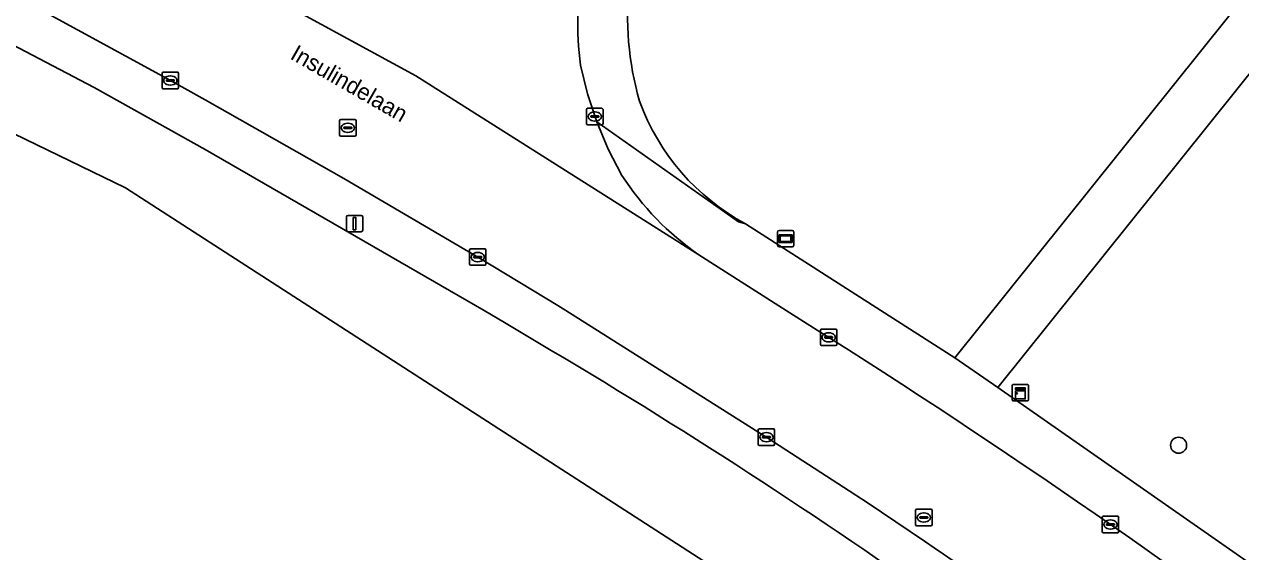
# Model space of a CAD drawing. Extents: x 162417 to 163722, y 384268 to 385417.
# Drawn here: x 162489 to 162563, y 384735.3 to 384767.4 of the extents above; entities that cross this region are included whole.
import ezdxf

# ---------------------------------------------------------------- set-up
doc = ezdxf.new("R2010")
doc.units = 0
for name, color, linetype in [('IMGEO_Berm_groen', 7, 'Continuous'), ('IMGEO_Boom', 7, 'Continuous'), ('IMGEO_Groenvoorziening', 7, 'Continuous'), ('IMGEO_Kast', 7, 'Continuous'), ('IMGEO_Kolk', 7, 'Continuous'), ('IMGEO_Lichtmast', 7, 'Continuous'), ('IMGEO_Openbare_ruimte_label', 7, 'Continuous'), ('IMGEO_Rijbaan_lokaal_open', 7, 'Continuous'), ('IMGEO_Rijbaan_regionaal_gesloten', 7, 'Continuous'), ('IMGEO_Rioolput', 7, 'Continuous'), ('IMGEO_Voetpad_gesloten', 7, 'Continuous'), ('IMGEO_Voetpad_open', 7, 'Continuous'), ('IMGEO_Wegwijzer', 7, 'Continuous')]:
    doc.layers.add(name, color=color, linetype=linetype)

msp = doc.modelspace()

# ---------------------------------------------------------------- linework, layer by layer
at = {"layer": 'IMGEO_Berm_groen'}
for points in [[(162466.355, 384777.285), (162477.959, 384771.545), (162479.839, 384770.588), (162493.238, 384763.558), (162500, 384759.787), (162516.963, 384750), (162518.198, 384749.269), (162519.432, 384748.535)], [(162543.752, 384735.979), (162540.261, 384738.331), (162534.228, 384742.243), (162521.936, 384750), (162521.444, 384750.302), (162516.728, 384753.165), (162508.438, 384758.029), (162500, 384762.81), (162497.883, 384763.979), (162489.507, 384768.547), (162481.057, 384772.976), (162479.187, 384773.932)]]:
    msp.add_lwpolyline(points, dxfattribs=at)
for centre, radius, start, end in [((162335.409, 384435.223), 363.358, 54.81641, 59.57224), ((162200.568, 384229.882), 611.482, 53.733687, 55.858809)]:
    msp.add_arc(centre, radius, start, end, dxfattribs=at)
at = {"layer": 'IMGEO_Boom'}
msp.add_circle((162559.218, 384741.808), 0.489, dxfattribs=at)
at = {"layer": 'IMGEO_Groenvoorziening'}
for points in [[(162532.879, 384755.269), (162541.11, 384750), (162545.602, 384747.124), (162593.733, 384807.099)], [(162619.678, 384785.416), (162615.926, 384792.421), (162606.136, 384786.338), (162595.297, 384803.992), (162568.435, 384770.521), (162570.041, 384769.255), (162570.101, 384769.331), (162571.485, 384768.241), (162570.384, 384766.843), (162569, 384767.934), (162569.063, 384768.014), (162567.447, 384769.289), (162548.211, 384745.32), (162564.266, 384734.123)]]:
    msp.add_lwpolyline(points, dxfattribs=at)
for centre, radius, start, end in [((162544.214, 384767.888), 18.521, 173.44315, 196.21945), ((162539.387, 384767.421), 13.785, 199.96267, 241.82917)]:
    msp.add_arc(centre, radius, start, end, dxfattribs=at)
at = {"layer": 'IMGEO_Kast'}
for p, q in [((162549.091, 384744.577), (162549.091, 384745.418)), ((162549.091, 384745.418), (162549.091, 384744.577)), ((162549.166, 384745.502), (162550.007, 384745.502)), ((162550.007, 384745.502), (162549.166, 384745.502)), ((162550.091, 384745.427), (162550.091, 384744.586)), ((162550.091, 384744.586), (162550.091, 384745.427)), ((162550.016, 384744.502), (162549.175, 384744.502)), ((162549.175, 384744.502), (162550.016, 384744.502))]:
    msp.add_line(p, q, dxfattribs=at)
for points in [[(162549.286, 384745.292), (162549.886, 384745.292), (162549.886, 384745.207), (162549.286, 384745.207), (162549.286, 384745.292)], [(162549.286, 384745.117), (162549.886, 384745.117), (162549.886, 384744.628), (162549.286, 384744.628), (162549.286, 384745.117)]]:
    msp.add_lwpolyline(points, dxfattribs=at)
msp.add_circle((162549.37, 384744.966), 0.0377, dxfattribs=at)
for centre, start, end in [((162549.169, 384745.424), 92.4484, 184.28452), ((162549.169, 384745.424), 92.4484, 184.28452), ((162550.013, 384745.424), 2.4484, 94.28452), ((162550.013, 384745.424), 2.4484, 94.28452), ((162549.169, 384744.58), 182.4484, 274.28452), ((162549.169, 384744.58), 182.4484, 274.28452), ((162550.013, 384744.58), 272.4484, 4.28452), ((162550.013, 384744.58), 272.4484, 4.28452)]:
    msp.add_arc(centre, 0.0779, start, end, dxfattribs=at)
at = {"layer": 'IMGEO_Kolk'}
for p, q in [((162497.453, 384764.48), (162498.305, 384764.48)), ((162497.378, 384763.554), (162497.378, 384764.406)), ((162497.637, 384763.974), (162497.637, 384763.986)), ((162498.075, 384763.937), (162497.677, 384763.937)), ((162497.68, 384764.023), (162498.078, 384764.023)), ((162497.866, 384764.26), (162497.891, 384764.26)), ((162498.121, 384763.986), (162498.121, 384763.974)), ((162498.379, 384764.406), (162498.379, 384763.554)), ((162498.305, 384763.48), (162497.453, 384763.48)), ((162497.889, 384763.7), (162497.864, 384763.7)), ((162523.276, 384762.29), (162524.128, 384762.29)), ((162523.201, 384761.364), (162523.201, 384762.216)), ((162523.46, 384761.784), (162523.46, 384761.796)), ((162523.898, 384761.747), (162523.5, 384761.747)), ((162523.503, 384761.833), (162523.901, 384761.833)), ((162523.712, 384761.51), (162523.687, 384761.51)), ((162523.689, 384762.07), (162523.714, 384762.07)), ((162523.944, 384761.796), (162523.944, 384761.784)), ((162524.202, 384762.216), (162524.202, 384761.364)), ((162524.128, 384761.29), (162523.276, 384761.29)), ((162516.079, 384752.82), (162516.079, 384753.672)), ((162516.154, 384753.746), (162517.006, 384753.746)), ((162516.567, 384753.526), (162516.592, 384753.526)), ((162517.08, 384753.672), (162517.08, 384752.82)), ((162517.006, 384752.746), (162516.154, 384752.746)), ((162516.338, 384753.24), (162516.338, 384753.252)), ((162516.776, 384753.203), (162516.378, 384753.203)), ((162516.381, 384753.289), (162516.779, 384753.289)), ((162516.59, 384752.966), (162516.565, 384752.966)), ((162516.822, 384753.252), (162516.822, 384753.24)), ((162537.428, 384747.94), (162537.428, 384748.792)), ((162537.503, 384748.866), (162538.355, 384748.866)), ((162537.687, 384748.36), (162537.687, 384748.372)), ((162538.125, 384748.323), (162537.727, 384748.323)), ((162537.73, 384748.409), (162538.128, 384748.409)), ((162537.916, 384748.646), (162537.941, 384748.646)), ((162538.171, 384748.372), (162538.171, 384748.36)), ((162538.429, 384748.792), (162538.429, 384747.94)), ((162538.355, 384747.866), (162537.503, 384747.866)), ((162537.939, 384748.086), (162537.914, 384748.086)), ((162533.642, 384741.873), (162533.642, 384742.725)), ((162533.717, 384742.799), (162534.569, 384742.799)), ((162533.901, 384742.293), (162533.901, 384742.305)), ((162534.339, 384742.256), (162533.941, 384742.256)), ((162533.944, 384742.342), (162534.342, 384742.342)), ((162534.13, 384742.579), (162534.155, 384742.579)), ((162534.385, 384742.305), (162534.385, 384742.293)), ((162534.643, 384742.725), (162534.643, 384741.873)), ((162534.569, 384741.799), (162533.717, 384741.799)), ((162534.153, 384742.019), (162534.128, 384742.019)), ((162554.57, 384736.564), (162554.57, 384737.416)), ((162554.645, 384737.49), (162555.497, 384737.49)), ((162555.058, 384737.27), (162555.083, 384737.27)), ((162555.571, 384737.416), (162555.571, 384736.564)), ((162555.497, 384736.49), (162554.645, 384736.49)), ((162554.829, 384736.984), (162554.829, 384736.996)), ((162555.267, 384736.947), (162554.869, 384736.947)), ((162554.872, 384737.033), (162555.27, 384737.033)), ((162555.081, 384736.71), (162555.056, 384736.71)), ((162555.313, 384736.996), (162555.313, 384736.984))]:
    msp.add_line(p, q, dxfattribs=at)
for points in [[(162497.453, 384764.48), (162498.305, 384764.48)], [(162497.378, 384763.554), (162497.378, 384764.406)], [(162498.379, 384764.406), (162498.379, 384763.554)], [(162498.305, 384763.48), (162497.453, 384763.48)], [(162523.276, 384762.29), (162524.128, 384762.29)], [(162523.201, 384761.364), (162523.201, 384762.216)], [(162524.202, 384762.216), (162524.202, 384761.364)], [(162524.128, 384761.29), (162523.276, 384761.29)], [(162516.079, 384752.82), (162516.079, 384753.672)], [(162516.154, 384753.746), (162517.006, 384753.746)], [(162517.08, 384753.672), (162517.08, 384752.82)], [(162517.006, 384752.746), (162516.154, 384752.746)], [(162537.428, 384747.94), (162537.428, 384748.792)], [(162537.503, 384748.866), (162538.355, 384748.866)], [(162538.429, 384748.792), (162538.429, 384747.94)], [(162538.355, 384747.866), (162537.503, 384747.866)], [(162533.642, 384741.873), (162533.642, 384742.725)], [(162533.717, 384742.799), (162534.569, 384742.799)], [(162534.643, 384742.725), (162534.643, 384741.873)], [(162534.569, 384741.799), (162533.717, 384741.799)], [(162554.57, 384736.564), (162554.57, 384737.416)], [(162554.645, 384737.49), (162555.497, 384737.49)], [(162555.571, 384737.416), (162555.571, 384736.564)], [(162555.497, 384736.49), (162554.645, 384736.49)]]:
    msp.add_lwpolyline(points, dxfattribs=at)
for centre, radius, start, end in [((162497.455, 384764.404), 0.0765, 91.55205, 178.44795), ((162497.455, 384764.404), 0.0765, 91.55205, 178.44795), ((162498.303, 384764.404), 0.0765, 1.55205, 88.44795), ((162498.303, 384764.404), 0.0765, 1.55205, 88.44795), ((162497.677, 384763.983), 0.0403, 85.87752, 175.75265), ((162497.674, 384763.973), 0.0366, 178.93798, 274.71019), ((162498.078, 384763.98), 0.043, 264.86636, 352.45326), ((162498.082, 384763.985), 0.0386, 1.73085, 96.63898), ((162497.455, 384763.556), 0.0765, 181.55205, 268.44795), ((162497.455, 384763.556), 0.0765, 181.55205, 268.44795), ((162498.303, 384763.556), 0.0765, 271.55205, 358.44795), ((162498.303, 384763.556), 0.0765, 271.55205, 358.44795), ((162523.278, 384762.214), 0.0765, 91.55205, 178.44795), ((162523.278, 384762.214), 0.0765, 91.55205, 178.44795), ((162524.126, 384762.214), 0.0765, 1.55205, 88.44795), ((162524.126, 384762.214), 0.0765, 1.55205, 88.44795), ((162523.5, 384761.793), 0.0403, 85.87752, 175.75265), ((162523.497, 384761.783), 0.0366, 178.93798, 274.71019), ((162523.901, 384761.79), 0.043, 264.86636, 352.45326), ((162523.905, 384761.795), 0.0386, 1.73085, 96.63898), ((162523.278, 384761.366), 0.0765, 181.55205, 268.44795), ((162523.278, 384761.366), 0.0765, 181.55205, 268.44795), ((162524.126, 384761.366), 0.0765, 271.55205, 358.44795), ((162524.126, 384761.366), 0.0765, 271.55205, 358.44795), ((162516.156, 384753.67), 0.0765, 91.55205, 178.44795), ((162516.156, 384753.67), 0.0765, 91.55205, 178.44795), ((162517.004, 384753.67), 0.0765, 1.55205, 88.44795), ((162517.004, 384753.67), 0.0765, 1.55205, 88.44795), ((162516.156, 384752.822), 0.0765, 181.55205, 268.44795), ((162516.156, 384752.822), 0.0765, 181.55205, 268.44795), ((162516.378, 384753.249), 0.0403, 85.87752, 175.75265), ((162516.375, 384753.239), 0.0366, 178.93798, 274.71019), ((162516.779, 384753.246), 0.043, 264.86636, 352.45326), ((162516.783, 384753.251), 0.0386, 1.73085, 96.63898), ((162517.004, 384752.822), 0.0765, 271.55205, 358.44795), ((162517.004, 384752.822), 0.0765, 271.55205, 358.44795), ((162537.505, 384748.79), 0.0765, 91.55205, 178.44795), ((162537.505, 384748.79), 0.0765, 91.55205, 178.44795), ((162537.727, 384748.369), 0.0403, 85.87752, 175.75265), ((162537.724, 384748.359), 0.0366, 178.93798, 274.71019), ((162538.128, 384748.366), 0.043, 264.86636, 352.45326), ((162538.132, 384748.371), 0.0386, 1.73085, 96.63898), ((162538.353, 384748.79), 0.0765, 1.55205, 88.44795), ((162538.353, 384748.79), 0.0765, 1.55205, 88.44795), ((162537.505, 384747.942), 0.0765, 181.55205, 268.44795), ((162537.505, 384747.942), 0.0765, 181.55205, 268.44795), ((162538.353, 384747.942), 0.0765, 271.55205, 358.44795), ((162538.353, 384747.942), 0.0765, 271.55205, 358.44795), ((162533.719, 384742.723), 0.0765, 91.55205, 178.44795), ((162533.719, 384742.723), 0.0765, 91.55205, 178.44795), ((162533.941, 384742.302), 0.0403, 85.87752, 175.75265), ((162533.938, 384742.292), 0.0366, 178.93798, 274.71019), ((162534.342, 384742.299), 0.043, 264.86636, 352.45326), ((162534.346, 384742.304), 0.0386, 1.73085, 96.63898), ((162534.567, 384742.723), 0.0765, 1.55205, 88.44795), ((162534.567, 384742.723), 0.0765, 1.55205, 88.44795), ((162533.719, 384741.875), 0.0765, 181.55205, 268.44795), ((162533.719, 384741.875), 0.0765, 181.55205, 268.44795), ((162534.567, 384741.875), 0.0765, 271.55205, 358.44795), ((162534.567, 384741.875), 0.0765, 271.55205, 358.44795), ((162554.647, 384737.414), 0.0765, 91.55205, 178.44795), ((162554.647, 384737.414), 0.0765, 91.55205, 178.44795), ((162555.495, 384737.414), 0.0765, 1.55205, 88.44795), ((162555.495, 384737.414), 0.0765, 1.55205, 88.44795), ((162554.647, 384736.566), 0.0765, 181.55205, 268.44795), ((162554.647, 384736.566), 0.0765, 181.55205, 268.44795), ((162554.869, 384736.993), 0.0403, 85.87752, 175.75265), ((162554.866, 384736.983), 0.0366, 178.93798, 274.71019), ((162555.27, 384736.99), 0.043, 264.86636, 352.45326), ((162555.274, 384736.995), 0.0386, 1.73085, 96.63898), ((162555.495, 384736.566), 0.0765, 271.55205, 358.44795), ((162555.495, 384736.566), 0.0765, 271.55205, 358.44795)]:
    msp.add_arc(centre, radius, start, end, dxfattribs=at)
for centre, major_axis, ratio, start_param, end_param in [((162497.865, 384763.98), (-0.387, 0.002), 0.722429, 4.712389, 7.853982), ((162497.89, 384763.98), (-0.39, 0.002), 0.717154, 1.570796, 4.712389), ((162523.688, 384761.79), (-0.387, 0.002), 0.722429, 4.712389, 7.853982), ((162523.713, 384761.79), (-0.39, 0.002), 0.717154, 1.570796, 4.712389), ((162516.566, 384753.246), (-0.387, 0.002), 0.722429, 4.712389, 7.853982), ((162516.591, 384753.246), (-0.39, 0.002), 0.717154, 1.570796, 4.712389), ((162537.915, 384748.366), (-0.387, 0.002), 0.722429, 4.712389, 7.853982), ((162537.94, 384748.366), (-0.39, 0.002), 0.717154, 1.570796, 4.712389), ((162534.129, 384742.299), (-0.387, 0.002), 0.722429, 4.712389, 7.853982), ((162534.154, 384742.299), (-0.39, 0.002), 0.717154, 1.570796, 4.712389), ((162555.057, 384736.99), (-0.387, 0.002), 0.722429, 4.712389, 7.853982), ((162555.082, 384736.99), (-0.39, 0.002), 0.717154, 1.570796, 4.712389)]:
    msp.add_ellipse(centre, major_axis=major_axis, ratio=ratio, start_param=start_param, end_param=end_param, dxfattribs=at)
at = {"layer": 'IMGEO_Lichtmast'}
for p, q in [((162508.59, 384754.884), (162508.59, 384755.684)), ((162508.59, 384755.684), (162508.59, 384754.884)), ((162508.69, 384755.784), (162509.48, 384755.784)), ((162509.48, 384755.784), (162508.69, 384755.784)), ((162509.58, 384755.684), (162509.58, 384754.884)), ((162509.58, 384754.884), (162509.58, 384755.684)), ((162509.48, 384754.784), (162508.69, 384754.784)), ((162508.69, 384754.784), (162509.48, 384754.784))]:
    msp.add_line(p, q, dxfattribs=at)
msp.add_lwpolyline([(162509.01, 384755.659), (162509.16, 384755.659), (162509.16, 384754.909), (162509.01, 384754.909), (162509.01, 384755.659)], dxfattribs=at)
for centre, start, end in [((162508.69, 384755.684), 90, 180), ((162508.69, 384755.684), 90, 180), ((162509.48, 384755.684), 0, 90), ((162509.48, 384755.684), 360, 90), ((162508.69, 384754.884), 180, 270), ((162508.69, 384754.884), 180, 270), ((162509.48, 384754.884), 270, 0), ((162509.48, 384754.884), 270, 0)]:
    msp.add_arc(centre, 0.1, start, end, dxfattribs=at)
at = {"layer": 'IMGEO_Rijbaan_lokaal_open'}
for points in [[(162539.129, 384747.613), (162537.23, 384748.802), (162535.35, 384750), (162531.214, 384752.635), (162530.024, 384753.387), (162512.819, 384764.272), (162493.067, 384775.022), (162489.507, 384768.547), (162497.883, 384763.979), (162500, 384762.81), (162508.438, 384758.029), (162516.728, 384753.165), (162521.444, 384750.302), (162521.936, 384750), (162534.228, 384742.243), (162540.261, 384738.331), (162543.752, 384735.979)], [(162496.132, 384774.163), (162494.962, 384774.352), (162494.006, 384774.664), (162493.067, 384775.022), (162512.819, 384764.272), (162530.024, 384753.387)], [(162525.353, 384758.214), (162524.522, 384759.807), (162523.822, 384761.461), (162523.257, 384763.166), (162522.832, 384764.911)]]:
    msp.add_lwpolyline(points, dxfattribs=at)
for centre, radius, start, end in [((162544.798, 384767.627), 22.134, 170.98768, 187.04798), ((162539.787, 384767.508), 17.167, 212.77721, 235.34085), ((162270.319, 384326.926), 499.236, 52.69511, 57.4223), ((162200.568, 384229.882), 611.482, 53.733687, 55.858809)]:
    msp.add_arc(centre, radius, start, end, dxfattribs=at)
at = {"layer": 'IMGEO_Rijbaan_regionaal_gesloten'}
for points in [[(162438.86, 384789.831), (162436.975, 384790.606), (162434.087, 384786.412), (162434.087, 384786.412), (162440.149, 384784.123), (162495.159, 384757.46), (162560.661, 384715.197), (162604.045, 384676.904), (162623.61, 384658.183), (162629.086, 384651.951)], [(162519.432, 384748.535), (162518.198, 384749.269), (162516.963, 384750), (162500, 384759.787), (162493.238, 384763.558), (162479.839, 384770.588), (162477.959, 384771.545), (162466.355, 384777.285)]]:
    msp.add_lwpolyline(points, dxfattribs=at)
msp.add_arc((162335.409, 384435.223), 363.358, 54.81641, 59.57224, dxfattribs=at)
at = {"layer": 'IMGEO_Rioolput'}
for p, q in [((162508.176, 384760.678), (162508.176, 384761.53)), ((162508.251, 384761.604), (162509.103, 384761.604)), ((162509.177, 384761.53), (162509.177, 384760.678)), ((162508.435, 384761.098), (162508.435, 384761.11)), ((162508.873, 384761.061), (162508.475, 384761.061)), ((162508.478, 384761.147), (162508.876, 384761.147)), ((162508.687, 384760.824), (162508.662, 384760.824)), ((162508.664, 384761.384), (162508.689, 384761.384)), ((162508.919, 384761.11), (162508.919, 384761.098)), ((162509.103, 384760.604), (162508.251, 384760.604)), ((162543.216, 384736.991), (162543.216, 384737.843)), ((162543.291, 384737.917), (162544.143, 384737.917)), ((162544.217, 384737.843), (162544.217, 384736.991)), ((162543.475, 384737.411), (162543.475, 384737.423)), ((162543.913, 384737.374), (162543.515, 384737.374)), ((162543.518, 384737.46), (162543.916, 384737.46)), ((162543.727, 384737.137), (162543.702, 384737.137)), ((162543.704, 384737.697), (162543.729, 384737.697)), ((162543.959, 384737.423), (162543.959, 384737.411)), ((162544.143, 384736.917), (162543.291, 384736.917))]:
    msp.add_line(p, q, dxfattribs=at)
for points in [[(162508.176, 384760.678), (162508.176, 384761.53)], [(162508.251, 384761.604), (162509.103, 384761.604)], [(162509.177, 384761.53), (162509.177, 384760.678)], [(162509.103, 384760.604), (162508.251, 384760.604)], [(162543.216, 384736.991), (162543.216, 384737.843)], [(162543.291, 384737.917), (162544.143, 384737.917)], [(162544.217, 384737.843), (162544.217, 384736.991)], [(162544.143, 384736.917), (162543.291, 384736.917)]]:
    msp.add_lwpolyline(points, dxfattribs=at)
for centre, radius, start, end in [((162508.253, 384761.528), 0.0765, 91.55205, 178.44795), ((162508.253, 384761.528), 0.0765, 91.55205, 178.44795), ((162509.101, 384761.528), 0.0765, 1.55205, 88.44795), ((162509.101, 384761.528), 0.0765, 1.55205, 88.44795), ((162508.475, 384761.107), 0.0403, 85.87752, 175.75265), ((162508.472, 384761.097), 0.0366, 178.93798, 274.71019), ((162508.876, 384761.104), 0.043, 264.86636, 352.45326), ((162508.88, 384761.109), 0.0386, 1.73085, 96.63898), ((162508.253, 384760.68), 0.0765, 181.55205, 268.44795), ((162508.253, 384760.68), 0.0765, 181.55205, 268.44795), ((162509.101, 384760.68), 0.0765, 271.55205, 358.44795), ((162509.101, 384760.68), 0.0765, 271.55205, 358.44795), ((162543.293, 384737.841), 0.0765, 91.55205, 178.44795), ((162543.293, 384737.841), 0.0765, 91.55205, 178.44795), ((162544.141, 384737.841), 0.0765, 1.55205, 88.44795), ((162544.141, 384737.841), 0.0765, 1.55205, 88.44795), ((162543.515, 384737.42), 0.0403, 85.87752, 175.75265), ((162543.512, 384737.41), 0.0366, 178.93798, 274.71019), ((162543.916, 384737.417), 0.043, 264.86636, 352.45326), ((162543.92, 384737.422), 0.0386, 1.73085, 96.63898), ((162543.293, 384736.993), 0.0765, 181.55205, 268.44795), ((162543.293, 384736.993), 0.0765, 181.55205, 268.44795), ((162544.141, 384736.993), 0.0765, 271.55205, 358.44795), ((162544.141, 384736.993), 0.0765, 271.55205, 358.44795)]:
    msp.add_arc(centre, radius, start, end, dxfattribs=at)
for centre, major_axis, ratio, start_param, end_param in [((162508.663, 384761.104), (-0.387, 0.002), 0.722429, 4.712389, 7.853982), ((162508.688, 384761.104), (-0.39, 0.002), 0.717154, 1.570796, 4.712389), ((162543.703, 384737.417), (-0.387, 0.002), 0.722429, 4.712389, 7.853982), ((162543.728, 384737.417), (-0.39, 0.002), 0.717154, 1.570796, 4.712389)]:
    msp.add_ellipse(centre, major_axis=major_axis, ratio=ratio, start_param=start_param, end_param=end_param, dxfattribs=at)
at = {"layer": 'IMGEO_Voetpad_gesloten'}
msp.add_lwpolyline([(162660.098, 384866.636), (162653.854, 384861.044), (162618.576, 384830.021), (162618.485, 384829.944), (162613.276, 384825.51), (162605.329, 384818.744), (162600.029, 384814.944), (162593.733, 384807.099), (162545.602, 384747.124), (162548.211, 384745.32), (162567.447, 384769.289), (162568.435, 384770.521), (162595.297, 384803.992), (162600.477, 384810.447), (162606.892, 384815.961)], dxfattribs=at)
at = {"layer": 'IMGEO_Voetpad_open'}
for points in [[(162522.832, 384764.911), (162523.257, 384763.166), (162523.822, 384761.461), (162532.445, 384755.385), (162532.879, 384755.269)], [(162564.266, 384734.123), (162548.211, 384745.32), (162545.602, 384747.124), (162541.11, 384750), (162532.879, 384755.269), (162532.445, 384755.385), (162523.822, 384761.461), (162524.522, 384759.807), (162525.353, 384758.214)], [(162530.024, 384753.387), (162531.214, 384752.635), (162535.35, 384750), (162537.23, 384748.802), (162539.129, 384747.613)]]:
    msp.add_lwpolyline(points, dxfattribs=at)
for centre, radius, start, end in [((162544.798, 384767.627), 22.134, 170.98768, 187.04798), ((162544.214, 384767.888), 18.521, 173.44315, 196.21945), ((162539.387, 384767.421), 13.785, 199.96267, 241.82917), ((162539.787, 384767.508), 17.167, 212.77721, 235.34085), ((162270.319, 384326.926), 499.236, 52.69511, 57.4223)]:
    msp.add_arc(centre, radius, start, end, dxfattribs=at)
at = {"layer": 'IMGEO_Wegwijzer'}
for p, q in [((162534.913, 384754.87), (162535.703, 384754.87)), ((162535.703, 384754.87), (162534.913, 384754.87)), ((162534.813, 384753.97), (162534.813, 384754.77)), ((162534.813, 384754.77), (162534.813, 384753.97)), ((162535.803, 384754.77), (162535.803, 384753.97)), ((162535.803, 384753.97), (162535.803, 384754.77)), ((162535.703, 384753.87), (162534.913, 384753.87)), ((162534.913, 384753.87), (162535.703, 384753.87))]:
    msp.add_line(p, q, dxfattribs=at)
for points in [[(162534.914, 384754.602), (162535.702, 384754.602), (162535.702, 384754.138), (162534.914, 384754.138), (162534.914, 384754.602)], [(162534.979, 384754.537), (162534.979, 384754.203), (162535.637, 384754.203), (162535.637, 384754.537), (162534.979, 384754.537)]]:
    msp.add_lwpolyline(points, dxfattribs=at)
for centre, start, end in [((162534.913, 384754.77), 90, 180), ((162534.913, 384754.77), 90, 180), ((162535.703, 384754.77), 0, 90), ((162535.703, 384754.77), 360, 90), ((162534.913, 384753.97), 180, 270), ((162534.913, 384753.97), 180, 270), ((162535.703, 384753.97), 270, 0), ((162535.703, 384753.97), 270, 0)]:
    msp.add_arc(centre, 0.1, start, end, dxfattribs=at)

# ---------------------------------------------------------------- texts
at = {"layer": 'IMGEO_Openbare_ruimte_label'}
msp.add_text('Insulindelaan', height=1, rotation=330.12718, dxfattribs=at).set_placement((162505.105, 384765.337))

doc.saveas('drawing.dxf')
